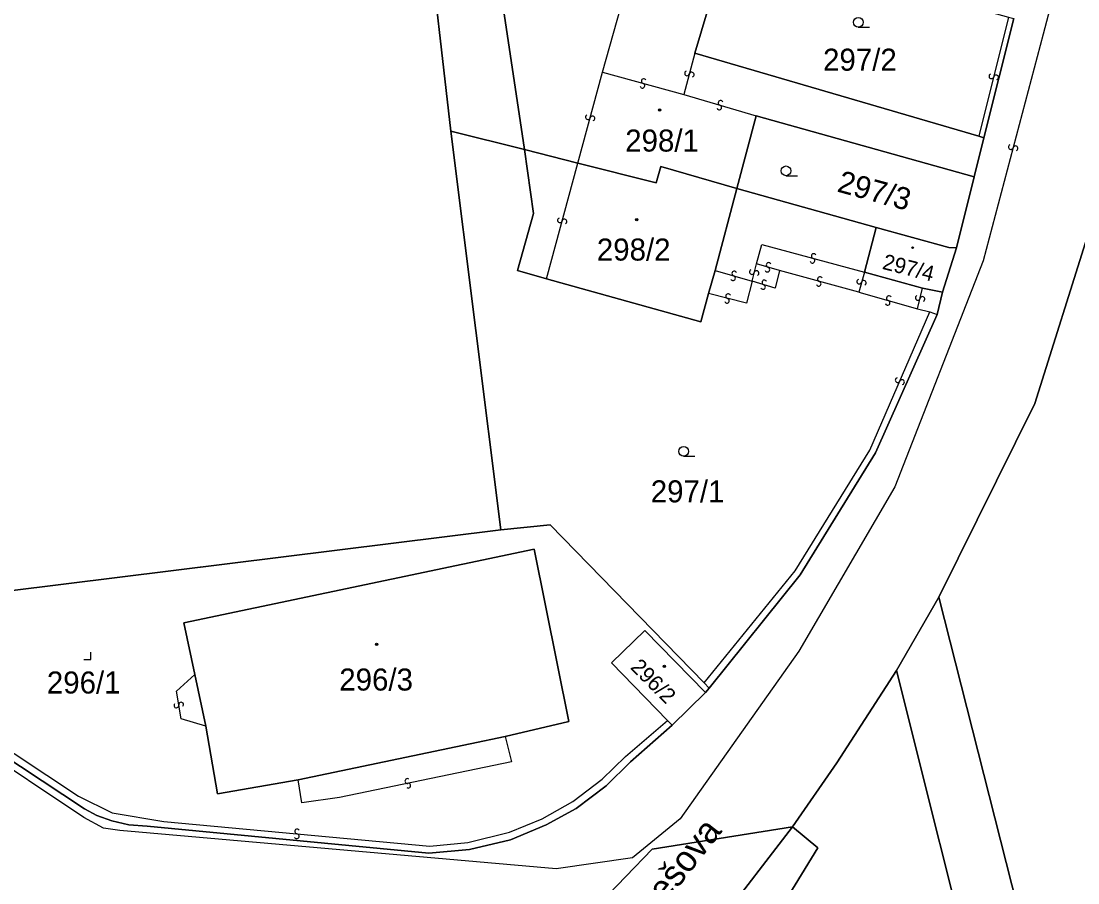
# Model space of a CAD drawing. Extents: x -600309 to -598967, y -1161267 to -1160292.
# Drawn here: x -599381.4 to -599299.8, y -1160704.1 to -1160637.6 of the extents above; entities that cross this region are included whole.
import ezdxf

# ---------------------------------------------------------------- set-up
doc = ezdxf.new("R2010")
doc.units = 0
for name, color, linetype in [('Level 1', 7, 'Continuous'), ('Level 11', 7, 'Continuous'), ('Level 13', 7, 'Continuous'), ('Level 3', 7, 'Continuous'), ('Level 4', 7, 'Continuous'), ('Level 5', 7, 'Continuous'), ('Level 60', 7, 'Continuous')]:
    doc.layers.add(name, color=color, linetype=linetype)

msp = doc.modelspace()

# ---------------------------------------------------------------- linework, layer by layer
at = {"layer": 'Level 1'}
for points in [[(-599348.21, -1160646.05), (-599350.07, -1160629.67)], [(-599333.61, -1160631.18), (-599336.43, -1160630.4), (-599340.13, -1160629.89), (-599343.48, -1160631.75), (-599344.14, -1160633.27), (-599344.08, -1160637), (-599342.52, -1160647.48)], [(-599329.36, -1160640.04), (-599327.23, -1160632.86), (-599333.61, -1160631.18)], [(-599304.75, -1160637.35), (-599307.05, -1160646.56)], [(-599329.36, -1160640.04), (-599307.44, -1160646.45)], [(-599326.13, -1160650.47), (-599324.63, -1160644.87)], [(-599324.63, -1160644.87), (-599307.8, -1160649.57)], [(-599348.21, -1160646.05), (-599342.52, -1160647.48)], [(-599344.33, -1160676.81), (-599348.21, -1160646.05)], [(-599307.05, -1160646.56), (-599307.8, -1160649.57)], [(-599307.05, -1160646.56), (-599307.44, -1160646.45)], [(-599342.52, -1160647.48), (-599341.83, -1160652.4), (-599343.06, -1160656.8), (-599340.81, -1160657.44)], [(-599338.39, -1160648.53), (-599342.52, -1160647.48)], [(-599326.13, -1160650.47), (-599332, -1160648.79), (-599332.35, -1160650.05), (-599338.39, -1160648.53)], [(-599307.8, -1160649.57), (-599309.17, -1160655.07)], [(-599327.8, -1160656.81), (-599326.13, -1160650.47)], [(-599326.13, -1160650.47), (-599315.38, -1160653.48)], [(-599315.38, -1160653.48), (-599316.28, -1160656.94)], [(-599309.17, -1160655.07), (-599309.76, -1160655.04), (-599315.38, -1160653.48)], [(-599310.54, -1160682.02), (-599303.13, -1160667.08), (-599298.92, -1160653.75)], [(-599309.17, -1160655.07), (-599310.25, -1160658.49)], [(-599328.3, -1160658.58), (-599327.8, -1160656.81)], [(-599316.28, -1160656.94), (-599311.79, -1160658.17)], [(-599340.81, -1160657.44), (-599328.9, -1160660.76), (-599328.3, -1160658.58)], [(-599311.79, -1160658.17), (-599310.25, -1160658.49)], [(-599310.25, -1160658.49), (-599310.67, -1160660.19)], [(-599328.26, -1160689.03), (-599321.24, -1160680.29), (-599315.41, -1160670.88), (-599310.67, -1160660.19)], [(-599328.64, -1160688.62), (-599340.53, -1160676.42), (-599344.33, -1160676.81)], [(-599344.33, -1160676.81), (-599390.75, -1160682.57)], [(-599367.95, -1160687.98), (-599368.8, -1160683.99), (-599341.77, -1160678.32), (-599339.09, -1160691.6), (-599344, -1160692.76)], [(-599313.81, -1160687.68), (-599310.54, -1160682.02)], [(-599305.42, -1160727.23), (-599300.58, -1160721.23), (-599310.54, -1160682.02)], [(-599328.54, -1160689.38), (-599333.22, -1160684.58), (-599335.79, -1160687.09), (-599331.47, -1160691.54)], [(-599367.11, -1160691.97), (-599367.95, -1160687.98)], [(-599321.84, -1160699.73), (-599318.4, -1160694.81), (-599313.81, -1160687.68)], [(-599313.81, -1160687.68), (-599307.13, -1160714.26), (-599307.25, -1160714.61), (-599307.53, -1160714.84), (-599307.88, -1160714.88), (-599308.17, -1160714.78)], [(-599328.26, -1160689.03), (-599328.64, -1160688.62)], [(-599331.12, -1160691.89), (-599328.54, -1160689.38)], [(-599328.54, -1160689.38), (-599328.26, -1160689.03)], [(-599384.71, -1160692.91), (-599376.48, -1160698.35), (-599375.53, -1160698.85), (-599374.36, -1160699.28), (-599373.06, -1160699.57), (-599371.64, -1160699.69), (-599349.91, -1160701.78), (-599346.76, -1160701.48), (-599343.6, -1160700.73), (-599340.83, -1160699.57), (-599338.53, -1160698.31), (-599336.2, -1160696.58), (-599334.32, -1160694.73), (-599331.12, -1160691.89)], [(-599359.98, -1160696.1), (-599366.22, -1160697.19), (-599367.11, -1160691.97)], [(-599331.12, -1160691.89), (-599331.47, -1160691.54)], [(-599344, -1160692.76), (-599346.72, -1160693.32), (-599359.98, -1160696.1)], [(-599321.84, -1160699.73), (-599332.66, -1160701.45), (-599344.85, -1160714.12)], [(-599335.65, -1160726.3), (-599339.05, -1160722.11), (-599321.84, -1160699.73)], [(-599333.16, -1160724.45), (-599333.67, -1160723.86), (-599319.88, -1160701.35), (-599321.84, -1160699.73)]]:
    msp.add_lwpolyline(points, dxfattribs=at)
at = {"layer": 'Level 13'}
for centre, start, end in [((-599329.968, -1160641.591), 112.07047, 344.66047), ((-599329.612, -1160641.69), 292.28492, 164.38292), ((-599306.478, -1160641.815), 113.21018, 345.80018), ((-599333.409, -1160642.547), 201.84142, 74.43142), ((-599333.31, -1160642.193), 22.05587, 254.15387), ((-599306.121, -1160641.906), 293.42464, 165.52263), ((-599327.483, -1160644.226), 200.80759, 73.39759), ((-599327.376, -1160643.874), 21.02204, 253.12004), ((-599337.628, -1160644.97), 112.30424, 344.40224), ((-599337.272, -1160645.069), 292.08979, 164.67979), ((-599304.978, -1160647.282), 112.30029, 344.89029), ((-599304.622, -1160647.379), 292.51474, 164.61274), ((-599339.778, -1160652.93), 112.17749, 344.27548), ((-599339.423, -1160653.029), 291.96303, 164.55303), ((-599320.19, -1160655.692), 22.25237, 254.35037), ((-599323.669, -1160656.383), 21.33908, 253.92908), ((-599320.289, -1160656.047), 202.03791, 74.62791), ((-599326.318, -1160657.043), 21.37443, 253.47243), ((-599324.959, -1160656.925), 113.84442, 345.94242), ((-599324.601, -1160657.014), 293.62996, 166.21996), ((-599323.772, -1160656.737), 201.55354, 73.65154), ((-599326.422, -1160657.397), 201.15998, 73.74998), ((-599324.105, -1160658.076), 200.49647, 72.59447), ((-599323.996, -1160657.724), 20.28201, 252.87201), ((-599319.811, -1160657.827), 201.99866, 74.09666), ((-599319.71, -1160657.473), 21.78421, 254.37421), ((-599316.677, -1160657.66), 111.65323, 344.24323), ((-599316.323, -1160657.761), 291.86769, 163.96569), ((-599326.793, -1160658.782), 22.52138, 255.11138), ((-599314.389, -1160658.943), 21.74453, 253.84253), ((-599312.159, -1160658.915), 113.93153, 346.02953), ((-599311.801, -1160659.004), 293.71707, 166.30707), ((-599326.888, -1160659.138), 202.73583, 74.83383), ((-599314.49, -1160659.297), 201.53008, 74.12008), ((-599313.708, -1160665.265), 103.84475, 335.94275), ((-599313.372, -1160665.414), 283.63029, 156.22029), ((-599369.382, -1160690.369), 136.96587, 9.06386), ((-599369.018, -1160690.31), 316.75141, 189.34141), ((-599351.557, -1160696.2), 48.87456, 281.46456), ((-599351.484, -1160696.561), 229.08901, 101.18701), ((-599360.098, -1160700.463), 211.81024, 84.40024), ((-599360.061, -1160700.097), 32.0247, 264.12269)]:
    msp.add_arc(centre, 0.184, start, end, dxfattribs=at)
at = {"layer": 'Level 3'}
for points in [[(-599269.57, -1160445.96), (-599268.6, -1160466.48), (-599267.81, -1160480.66), (-599268.38, -1160504.97), (-599271.49, -1160520.31), (-599275.91, -1160537.29), (-599281.9, -1160560.17), (-599289.04, -1160587.33), (-599298.86, -1160624.79), (-599302.48, -1160638.58), (-599307.12, -1160656.07), (-599313.94, -1160673.49), (-599321.33, -1160686.18), (-599330.51, -1160699.12), (-599334.17, -1160702.12), (-599340.08, -1160702.99), (-599373.75, -1160700.03), (-599375, -1160699.84), (-599376.53, -1160699.02), (-599385.16, -1160693.25)], [(-599336.5, -1160641.51), (-599333.72, -1160631.63), (-599333.61, -1160631.18)], [(-599305.16, -1160637.27), (-599307.44, -1160646.45)], [(-599329.36, -1160640.04), (-599330.22, -1160643.23)], [(-599338.39, -1160648.53), (-599336.5, -1160641.51)], [(-599336.5, -1160641.51), (-599330.22, -1160643.23)], [(-599330.22, -1160643.23), (-599324.63, -1160644.87)], [(-599340.81, -1160657.44), (-599338.39, -1160648.53)], [(-599324.62, -1160656.3), (-599324.2, -1160654.8), (-599316.28, -1160656.94)], [(-599324.94, -1160657.63), (-599324.62, -1160656.3)], [(-599322.82, -1160656.81), (-599324.62, -1160656.3)], [(-599327.8, -1160656.81), (-599324.94, -1160657.63)], [(-599322.82, -1160656.81), (-599323.16, -1160658.17), (-599324.94, -1160657.63)], [(-599316.71, -1160658.49), (-599322.82, -1160656.81)], [(-599316.28, -1160656.94), (-599316.71, -1160658.49)], [(-599324.94, -1160657.63), (-599325.39, -1160659.34), (-599328.3, -1160658.58)], [(-599316.71, -1160658.49), (-599312.17, -1160659.76)], [(-599312.17, -1160659.76), (-599311.79, -1160658.17)], [(-599328.64, -1160688.62), (-599321.63, -1160679.97), (-599315.87, -1160670.68), (-599311.22, -1160660)], [(-599312.17, -1160659.76), (-599311.22, -1160660)], [(-599311.22, -1160660), (-599310.67, -1160660.19)], [(-599367.11, -1160691.97), (-599369.02, -1160691.41), (-599369.38, -1160689.28), (-599367.95, -1160687.98)], [(-599384.71, -1160692.91), (-599384.38, -1160692.47), (-599376.93, -1160697.37), (-599374.35, -1160698.65), (-599370.34, -1160699.32), (-599349.83, -1160701.24), (-599346.9, -1160700.95), (-599343.67, -1160700.16), (-599341.16, -1160699.13), (-599338.79, -1160697.78), (-599336.51, -1160696.06), (-599334.73, -1160694.31), (-599331.47, -1160691.54)], [(-599344, -1160692.76), (-599343.52, -1160694.71), (-599346.24, -1160695.28), (-599356.8, -1160697.47), (-599359.69, -1160697.89), (-599359.98, -1160696.1)]]:
    msp.add_lwpolyline(points, dxfattribs=at)
at = {"layer": 'Level 5'}
for p, q in [((-599316.75, -1160638.03), (-599315.875, -1160638.03)), ((-599322.33, -1160649.49), (-599321.455, -1160649.49)), ((-599330.23, -1160671.14), (-599329.355, -1160671.14))]:
    msp.add_line(p, q, dxfattribs=at)
msp.add_lwpolyline([(-599376.53, -1160686.82), (-599375.98, -1160686.82), (-599375.98, -1160686.27)], dxfattribs=at)
for centre, radius in [((-599316.75, -1160637.655), 0.375), ((-599332.09, -1160644.42), 0.09), ((-599332.09, -1160644.42), 0.0521), ((-599322.33, -1160649.115), 0.375), ((-599333.85, -1160652.88), 0.09), ((-599333.85, -1160652.88), 0.0521), ((-599312.56, -1160655.05), 0.0612), ((-599312.56, -1160655.05), 0.0354), ((-599330.23, -1160670.765), 0.375), ((-599353.93, -1160685.65), 0.09), ((-599353.93, -1160685.65), 0.0521), ((-599331.72, -1160687.35), 0.09), ((-599331.72, -1160687.35), 0.0521)]:
    msp.add_circle(centre, radius, dxfattribs=at)
at = {"layer": 'Level 60'}
for points in [[(-599348.21, -1160646.05), (-599344.33, -1160676.81), (-599390.75, -1160682.57), (-599434.16, -1160653.71), (-599461.15, -1160591.17), (-599413.91, -1160590.39), (-599393.85, -1160579.06), (-599380.27, -1160575.77), (-599376.56, -1160574.61), (-599358.54, -1160569), (-599357.92, -1160570.93), (-599354.89, -1160593.32), (-599350.07, -1160629.67)], [(-599342.52, -1160647.48), (-599348.21, -1160646.05), (-599350.07, -1160629.67), (-599337.82, -1160628.16), (-599305.16, -1160637.27), (-599304.75, -1160637.35), (-599307.05, -1160646.56), (-599307.44, -1160646.45), (-599329.36, -1160640.04), (-599327.23, -1160632.86), (-599333.61, -1160631.18), (-599336.43, -1160630.4), (-599340.13, -1160629.89), (-599343.48, -1160631.75), (-599344.14, -1160633.27), (-599344.08, -1160637)], [(-599327.23, -1160632.86), (-599329.36, -1160640.04), (-599307.44, -1160646.45), (-599307.05, -1160646.56), (-599307.8, -1160649.57), (-599324.63, -1160644.87), (-599326.13, -1160650.47), (-599332, -1160648.79), (-599332.35, -1160650.05), (-599338.39, -1160648.53), (-599342.52, -1160647.48), (-599344.08, -1160637), (-599344.14, -1160633.27), (-599343.48, -1160631.75), (-599340.13, -1160629.89), (-599336.43, -1160630.4), (-599333.61, -1160631.18)], [(-599315.38, -1160653.48), (-599326.13, -1160650.47), (-599324.63, -1160644.87), (-599307.8, -1160649.57), (-599309.17, -1160655.07), (-599309.76, -1160655.04)], [(-599348.21, -1160646.05), (-599342.52, -1160647.48), (-599341.83, -1160652.4), (-599343.06, -1160656.8), (-599340.81, -1160657.44), (-599328.9, -1160660.76), (-599328.3, -1160658.58), (-599327.8, -1160656.81), (-599326.13, -1160650.47), (-599315.38, -1160653.48), (-599316.28, -1160656.94), (-599311.79, -1160658.17), (-599310.25, -1160658.49), (-599310.67, -1160660.19), (-599315.41, -1160670.88), (-599321.24, -1160680.29), (-599328.26, -1160689.03), (-599328.64, -1160688.62), (-599340.53, -1160676.42), (-599344.33, -1160676.81)], [(-599341.83, -1160652.4), (-599342.52, -1160647.48), (-599338.39, -1160648.53), (-599332.35, -1160650.05), (-599332, -1160648.79), (-599326.13, -1160650.47), (-599327.8, -1160656.81), (-599328.3, -1160658.58), (-599328.9, -1160660.76), (-599340.81, -1160657.44), (-599343.06, -1160656.8)], [(-599316.28, -1160656.94), (-599315.38, -1160653.48), (-599309.76, -1160655.04), (-599309.17, -1160655.07), (-599310.25, -1160658.49), (-599311.79, -1160658.17)], [(-599328.64, -1160688.62), (-599328.26, -1160689.03), (-599328.54, -1160689.38), (-599333.22, -1160684.58), (-599335.79, -1160687.09), (-599331.47, -1160691.54), (-599331.12, -1160691.89), (-599334.32, -1160694.73), (-599336.2, -1160696.58), (-599338.53, -1160698.31), (-599340.83, -1160699.57), (-599343.6, -1160700.73), (-599346.76, -1160701.48), (-599349.91, -1160701.78), (-599371.64, -1160699.69), (-599373.06, -1160699.57), (-599374.36, -1160699.28), (-599375.53, -1160698.85), (-599376.48, -1160698.35), (-599384.71, -1160692.91), (-599390.75, -1160682.57), (-599344.33, -1160676.81), (-599340.53, -1160676.42)], [(-599341.77, -1160678.32), (-599368.8, -1160683.99), (-599367.95, -1160687.98), (-599367.11, -1160691.97), (-599366.22, -1160697.19), (-599359.98, -1160696.1), (-599346.72, -1160693.32), (-599344, -1160692.76), (-599339.09, -1160691.6)], [(-599368.8, -1160683.99), (-599341.77, -1160678.32), (-599339.09, -1160691.6), (-599344, -1160692.76), (-599346.72, -1160693.32), (-599359.98, -1160696.1), (-599366.22, -1160697.19), (-599367.11, -1160691.97), (-599367.95, -1160687.98)], [(-599307.13, -1160714.26), (-599313.81, -1160687.68), (-599310.54, -1160682.02), (-599300.58, -1160721.23), (-599305.42, -1160727.23), (-599307.56, -1160729.96), (-599309.46, -1160732.28), (-599311.28, -1160734.52), (-599313.18, -1160736.83), (-599315.31, -1160739.49), (-599324.88, -1160724.45), (-599319.47, -1160728.7), (-599317.5, -1160726.31), (-599315.14, -1160723.39), (-599313.12, -1160720.89), (-599311.03, -1160718.24), (-599308.17, -1160714.78), (-599307.88, -1160714.88), (-599307.53, -1160714.84), (-599307.25, -1160714.61)], [(-599328.54, -1160689.38), (-599331.12, -1160691.89), (-599331.47, -1160691.54), (-599335.79, -1160687.09), (-599333.22, -1160684.58)], [(-599335.65, -1160726.3), (-599340.56, -1160734.48), (-599344.39, -1160735.76), (-599345.4, -1160733.39), (-599346.82, -1160730.49), (-599350.84, -1160721.89), (-599351.05, -1160721.44), (-599346.43, -1160715.76), (-599344.85, -1160714.12), (-599332.66, -1160701.45), (-599321.84, -1160699.73), (-599339.05, -1160722.11)], [(-599319.88, -1160701.35), (-599333.67, -1160723.86), (-599333.16, -1160724.45), (-599335.27, -1160725.67), (-599335.65, -1160726.3), (-599339.05, -1160722.11), (-599321.84, -1160699.73)]]:
    msp.add_lwpolyline(points, close=True, dxfattribs=at)
for points in [[(-599384.71, -1160692.91), (-599376.48, -1160698.35), (-599375.53, -1160698.85), (-599374.36, -1160699.28), (-599373.06, -1160699.57), (-599371.64, -1160699.69), (-599349.91, -1160701.78), (-599346.76, -1160701.48), (-599343.6, -1160700.73), (-599340.83, -1160699.57), (-599338.53, -1160698.31), (-599336.2, -1160696.58), (-599334.32, -1160694.73), (-599331.12, -1160691.89), (-599328.54, -1160689.38), (-599328.26, -1160689.03), (-599321.24, -1160680.29), (-599315.41, -1160670.88), (-599310.67, -1160660.19), (-599310.25, -1160658.49), (-599309.17, -1160655.07), (-599307.8, -1160649.57), (-599307.05, -1160646.56), (-599304.75, -1160637.35)], [(-599298.92, -1160653.75), (-599303.13, -1160667.08), (-599310.54, -1160682.02), (-599313.81, -1160687.68), (-599318.4, -1160694.81), (-599321.84, -1160699.73), (-599332.66, -1160701.45), (-599344.85, -1160714.12), (-599346.43, -1160715.76), (-599345.9, -1160714.27), (-599345.9, -1160712.61), (-599346.38, -1160711.21), (-599346.93, -1160710.13), (-599347.86, -1160709.29), (-599349.11, -1160708.83), (-599372, -1160706.66), (-599374.96, -1160706.57), (-599377.59, -1160706.64), (-599381.59, -1160707.31)], [(-599300.58, -1160721.23), (-599310.54, -1160682.02), (-599303.13, -1160667.08), (-599298.92, -1160653.75)], [(-599333.67, -1160723.86), (-599319.88, -1160701.35), (-599321.84, -1160699.73), (-599318.4, -1160694.81), (-599313.81, -1160687.68), (-599307.13, -1160714.26)]]:
    msp.add_lwpolyline(points, dxfattribs=at)

# ---------------------------------------------------------------- texts
at = {"layer": 'Level 11'}
msp.add_text('Tomešova', height=2, rotation=51.82678, dxfattribs=at).set_placement((-599334.931, -1160709.892))
at = {"layer": 'Level 4'}
for s, p in [('297/2', (-599319.47, -1160641.39)), ('298/1', (-599334.74, -1160647.63)), ('298/2', (-599336.93, -1160656.04)), ('297/1', (-599332.77, -1160674.7)), ('296/1', (-599379.38, -1160689.45)), ('296/3', (-599356.81, -1160689.22))]:
    msp.add_text(s, height=1.7, dxfattribs=at).set_placement(p)
for s, height, rotation, p in [('297/3', 1.7, 344.7, (-599318.46, -1160650.7)), ('297/4', 1.2, 345.6, (-599314.96, -1160656.67)), ('296/2', 1.2, 315, (-599334.41, -1160687.49))]:
    msp.add_text(s, height=height, rotation=rotation, dxfattribs=at).set_placement(p)

doc.saveas('drawing.dxf')
